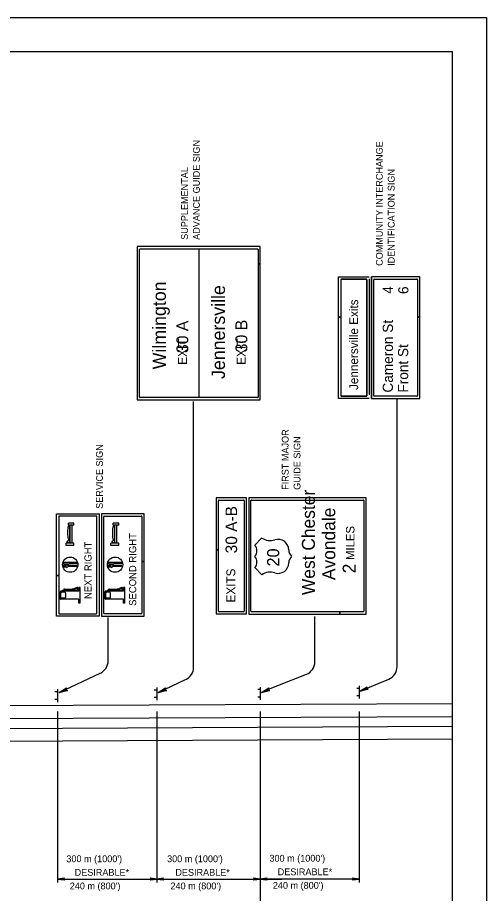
# Model space of a CAD drawing. Extents: x 640994 to 644422, y 298458 to 299646.
# Drawn here: x 644151 to 644358.3, y 299258.5 to 299645.6 of the extents above; entities that cross this region are included whole.
import ezdxf

# ---------------------------------------------------------------- set-up
doc = ezdxf.new("R2010")
doc.units = 0
for name, color, linetype in [('1', 7, 'Continuous'), ('2', 7, 'Continuous'), ('XCS-GRID-MIN', 7, 'Continuous')]:
    doc.layers.add(name, color=color, linetype=linetype)

msp = doc.modelspace()

# ---------------------------------------------------------------- linework, layer by layer
at = {"layer": '1'}
for p in [(643557.31, 299630.63), (644343.31, 299066.63)]:
    msp.add_line(p, (644343.31, 299630.63), dxfattribs=at)
at = {"layer": '2'}
for p, q in [((644258.31, 299544.39), (644203.94, 299544.39)), ((644203.94, 299544.39), (644203.94, 299476.64)), ((644258.31, 299536.79), (644258.31, 299544.39)), ((644204.94, 299477.89), (644204.94, 299543.14)), ((644205.19, 299543.39), (644257.06, 299543.39)), ((644231.19, 299543.39), (644231.19, 299477.64)), ((644257.31, 299543.14), (644257.31, 299536.79)), ((644258.31, 299536.79), (644257.31, 299536.79)), ((644257.31, 299536.79), (644257.31, 299477.89)), ((644257.31, 299536.79), (644258.31, 299536.79)), ((644258.31, 299476.64), (644258.31, 299536.79)), ((644292.94, 299513.21), (644292.94, 299531.02)), ((644292.94, 299531.02), (644306.44, 299531.02)), ((644293.94, 299529.77), (644293.94, 299513.21)), ((644294.19, 299530.02), (644305.19, 299530.02)), ((644305.19, 299530.02), (644294.19, 299530.02)), ((644305.44, 299529.77), (644305.44, 299478.52)), ((644305.44, 299478.52), (644305.44, 299529.77)), ((644306.44, 299530.14), (644306.44, 299478.89)), ((644307.44, 299477.27), (644307.44, 299531.02)), ((644328.81, 299531.02), (644307.44, 299531.02)), ((644307.44, 299531.02), (644307.44, 299477.27)), ((644308.44, 299478.52), (644308.44, 299529.77)), ((644308.44, 299478.52), (644308.44, 299529.77)), ((644308.69, 299530.02), (644327.56, 299530.02)), ((644308.69, 299530.02), (644327.56, 299530.02)), ((644327.81, 299529.77), (644327.81, 299513.28)), ((644328.81, 299513.28), (644328.81, 299531.02)), ((644292.94, 299513.21), (644293.94, 299513.21)), ((644293.94, 299513.21), (644292.94, 299513.21)), ((644292.94, 299477.27), (644292.94, 299513.21)), ((644293.94, 299513.21), (644293.94, 299478.52)), ((644299.69, 299515.27), (644299.69, 299515.27)), ((644327.81, 299513.28), (644328.81, 299513.28)), ((644328.81, 299513.28), (644327.81, 299513.28)), ((644327.81, 299513.28), (644327.81, 299478.52)), ((644328.81, 299477.27), (644328.81, 299513.28)), ((644318.19, 299504.14), (644318.19, 299504.14)), ((644257.06, 299477.64), (644205.19, 299477.64)), ((644305.19, 299478.27), (644294.19, 299478.27)), ((644294.19, 299478.27), (644305.19, 299478.27)), ((644327.56, 299478.27), (644308.69, 299478.27)), ((644327.56, 299478.27), (644308.69, 299478.27)), ((644203.94, 299476.64), (644258.31, 299476.64)), ((644228.81, 299358.52), (644228.81, 299475.89)), ((644306.44, 299477.27), (644292.94, 299477.27)), ((644307.44, 299477.27), (644307.41, 299477.27)), ((644307.44, 299477.27), (644328.81, 299477.27)), ((644318.81, 299358.77), (644318.81, 299476.77)), ((644252.19, 299433.34), (644238.81, 299433.34)), ((644238.81, 299433.34), (644238.81, 299410.41)), ((644239.81, 299410.41), (644239.81, 299432.09)), ((644240.06, 299432.34), (644250.94, 299432.34)), ((644251.19, 299432.09), (644251.19, 299383.31)), ((644252.19, 299382.06), (644252.19, 299433.34)), ((644305.06, 299433.39), (644253.19, 299433.39)), ((644253.19, 299433.39), (644253.19, 299382.02)), ((644254.19, 299383.27), (644254.19, 299432.14)), ((644254.44, 299432.39), (644303.81, 299432.39)), ((644304.06, 299432.14), (644304.06, 299383.27)), ((644305.06, 299382.02), (644305.06, 299433.39)), ((644168.19, 299399.01), (644168.19, 299426.27)), ((644168.19, 299426.27), (644187.06, 299426.27)), ((644169.19, 299425.02), (644169.19, 299399.01)), ((644185.81, 299425.27), (644169.44, 299425.27)), ((644186.06, 299382.39), (644186.06, 299425.02)), ((644187.06, 299426.27), (644187.06, 299381.14)), ((644206.94, 299426.27), (644188.06, 299426.27)), ((644188.06, 299426.27), (644188.06, 299381.14)), ((644189.06, 299382.39), (644189.06, 299425.02)), ((644189.31, 299425.27), (644205.69, 299425.27)), ((644205.94, 299425.02), (644205.94, 299405.17)), ((644206.94, 299405.17), (644206.94, 299426.27)), ((644175.94, 299422.14), (644173.44, 299422.14)), ((644173.44, 299421.27), (644173.44, 299422.14)), ((644175.94, 299421.27), (644173.44, 299421.27)), ((644174.06, 299414.77), (644174.06, 299421.02)), ((644174.31, 299413.27), (644174.31, 299421.27)), ((644175.19, 299413.27), (644175.19, 299421.27)), ((644175.94, 299421.27), (644175.94, 299422.14)), ((644195.81, 299422.14), (644193.31, 299422.14)), ((644193.31, 299421.27), (644193.31, 299422.14)), ((644195.81, 299421.27), (644193.31, 299421.27)), ((644193.94, 299414.77), (644193.94, 299421.02)), ((644194.06, 299413.27), (644194.06, 299421.27)), ((644194.94, 299413.27), (644194.94, 299421.27)), ((644195.81, 299421.27), (644195.81, 299422.14)), ((644174.31, 299417.27), (644174.31, 299417.27)), ((644174.31, 299417.27), (644174.31, 299417.27)), ((644194.06, 299417.27), (644194.06, 299417.27)), ((644194.06, 299417.27), (644194.06, 299417.27)), ((644175.94, 299413.27), (644172.44, 299413.27)), ((644172.44, 299412.27), (644172.44, 299413.27)), ((644175.94, 299412.27), (644172.44, 299412.27)), ((644175.94, 299412.27), (644175.94, 299413.27)), ((644195.81, 299413.27), (644192.19, 299413.27)), ((644192.19, 299412.27), (644192.19, 299413.27)), ((644195.81, 299412.27), (644192.19, 299412.27)), ((644195.81, 299412.27), (644195.81, 299413.27)), ((644255.94, 299412.52), (644259.06, 299415.64)), ((644266.19, 299415.02), (644266.19, 299415.02)), ((644239.81, 299410.41), (644238.81, 299410.41)), ((644238.81, 299410.41), (644238.81, 299382.06)), ((644238.81, 299410.41), (644239.81, 299410.41)), ((644239.81, 299383.31), (644239.81, 299410.41)), ((644270.94, 299410.39), (644270.94, 299410.39)), ((644177.06, 299404.77), (644171.31, 299404.77)), ((644171.31, 299404.77), (644171.31, 299404.39)), ((644177.06, 299404.27), (644174.06, 299404.27)), ((644196.81, 299404.77), (644191.06, 299404.77)), ((644191.06, 299404.77), (644191.06, 299404.39)), ((644196.81, 299404.27), (644193.94, 299404.27)), ((644205.94, 299405.17), (644206.94, 299405.17)), ((644206.94, 299405.17), (644205.94, 299405.17)), ((644205.94, 299405.17), (644205.94, 299382.39)), ((644206.94, 299381.14), (644206.94, 299405.17)), ((644264.19, 299407.52), (644264.19, 299407.52)), ((644264.19, 299407.52), (644264.19, 299407.52)), ((644270.94, 299404.64), (644270.94, 299404.64)), ((644171.19, 299403.52), (644172.44, 299403.77)), ((644172.56, 299403.52), (644171.19, 299403.52)), ((644171.19, 299403.02), (644172.31, 299403.14)), ((644172.69, 299402.89), (644171.19, 299403.02)), ((644172.56, 299402.64), (644171.19, 299402.89)), ((644171.19, 299402.89), (644172.69, 299402.89)), ((644171.31, 299403.39), (644172.56, 299403.52)), ((644172.56, 299403.27), (644171.31, 299403.39)), ((644173.44, 299404.02), (644171.81, 299404.02)), ((644172.31, 299403.14), (644172.56, 299403.27)), ((644177.06, 299403.39), (644173.56, 299403.39)), ((644177.06, 299403.02), (644173.56, 299403.02)), ((644174.31, 299403.77), (644174.31, 299403.77)), ((644174.31, 299403.77), (644174.31, 299403.77)), ((644177.69, 299403.77), (644177.69, 299403.77)), ((644191.06, 299403.52), (644192.19, 299403.77)), ((644191.06, 299403.39), (644192.44, 299403.52)), ((644192.44, 299403.52), (644191.06, 299403.52)), ((644192.44, 299403.27), (644191.06, 299403.39)), ((644191.06, 299403.02), (644192.19, 299403.14)), ((644192.44, 299402.89), (644191.06, 299403.02)), ((644192.31, 299402.64), (644191.06, 299402.89)), ((644191.06, 299402.89), (644192.44, 299402.89)), ((644193.19, 299404.02), (644191.56, 299404.02)), ((644192.19, 299403.14), (644192.44, 299403.27)), ((644196.81, 299403.39), (644193.31, 299403.39)), ((644196.81, 299403.02), (644193.31, 299403.02)), ((644194.06, 299403.77), (644194.06, 299403.77)), ((644194.06, 299403.77), (644194.06, 299403.77)), ((644197.44, 299403.77), (644197.44, 299403.77)), ((644259.06, 299399.39), (644255.94, 299402.52)), ((644168.19, 299381.14), (644168.19, 299399.01)), ((644168.19, 299399.01), (644169.19, 299399.01)), ((644169.19, 299399.01), (644168.19, 299399.01)), ((644169.19, 299399.01), (644169.19, 299382.39)), ((644170.56, 299392.14), (644171.19, 299392.77)), ((644171.81, 299393.02), (644174.94, 299393.02)), ((644172.06, 299392.77), (644174.94, 299392.77)), ((644172.06, 299392.77), (644172.06, 299392.27)), ((644173.44, 299392.52), (644176.81, 299392.52)), ((644175.56, 299393.14), (644176.44, 299393.52)), ((644175.81, 299392.89), (644176.56, 299393.14)), ((644178.06, 299392.14), (644178.06, 299393.77)), ((644178.69, 299393.77), (644178.06, 299393.77)), ((644178.69, 299386.77), (644178.69, 299393.77)), ((644190.44, 299392.14), (644191.06, 299392.77)), ((644191.56, 299393.02), (644194.81, 299393.02)), ((644191.81, 299392.77), (644194.81, 299392.77)), ((644191.81, 299392.77), (644191.81, 299392.27)), ((644193.31, 299392.52), (644196.56, 299392.52)), ((644195.44, 299393.14), (644196.19, 299393.52)), ((644195.56, 299392.89), (644196.31, 299393.14)), ((644197.81, 299392.14), (644197.81, 299393.77)), ((644198.44, 299393.77), (644197.81, 299393.77)), ((644198.44, 299386.77), (644198.44, 299393.77)), ((644169.81, 299389.02), (644169.81, 299391.64)), ((644178.06, 299392.14), (644170.06, 299392.14)), ((644170.19, 299389.27), (644170.19, 299391.39)), ((644171.94, 299391.64), (644170.44, 299391.64)), ((644171.94, 299389.02), (644170.44, 299389.02)), ((644172.06, 299392.27), (644171.19, 299392.27)), ((644171.19, 299392.27), (644171.19, 299392.14)), ((644172.31, 299389.27), (644172.31, 299391.27)), ((644173.19, 299392.14), (644173.19, 299392.27)), ((644173.44, 299392.14), (644173.44, 299392.14)), ((644173.56, 299392.27), (644177.06, 299392.27)), ((644174.31, 299390.39), (644174.31, 299390.39)), ((644174.31, 299390.39), (644174.31, 299390.39)), ((644189.56, 299389.02), (644189.56, 299391.64)), ((644197.81, 299392.14), (644189.94, 299392.14)), ((644190.06, 299389.27), (644190.06, 299391.39)), ((644191.81, 299391.64), (644190.19, 299391.64)), ((644191.81, 299389.02), (644190.19, 299389.02)), ((644191.06, 299392.27), (644190.94, 299392.14)), ((644191.81, 299392.27), (644191.06, 299392.27)), ((644192.06, 299389.27), (644192.06, 299391.27)), ((644192.94, 299392.14), (644192.94, 299392.27)), ((644193.31, 299392.14), (644193.31, 299392.14)), ((644193.44, 299392.27), (644196.94, 299392.27)), ((644194.06, 299390.39), (644194.06, 299390.39)), ((644194.06, 299390.39), (644194.06, 299390.39)), ((644178.06, 299388.52), (644170.06, 299388.52)), ((644178.06, 299386.77), (644178.06, 299388.52)), ((644178.69, 299386.77), (644178.06, 299386.77)), ((644197.81, 299388.52), (644189.94, 299388.52)), ((644197.81, 299386.77), (644197.81, 299388.52)), ((644198.44, 299386.77), (644197.81, 299386.77)), ((644187.06, 299381.14), (644168.19, 299381.14)), ((644169.44, 299382.14), (644185.81, 299382.14)), ((644188.06, 299381.14), (644206.94, 299381.14)), ((644205.69, 299382.14), (644189.31, 299382.14)), ((644238.81, 299382.06), (644252.19, 299382.06)), ((644250.94, 299383.06), (644240.06, 299383.06)), ((644253.19, 299382.02), (644293.51, 299382.02)), ((644293.51, 299383.02), (644254.44, 299383.02)), ((644282.44, 299360.89), (644282.44, 299380.89)), ((644293.51, 299383.02), (644293.51, 299382.02)), ((644293.51, 299382.02), (644293.51, 299383.02)), ((644303.81, 299383.02), (644293.51, 299383.02)), ((644293.51, 299382.02), (644305.06, 299382.02)), ((644191.06, 299361.39), (644191.06, 299380.52)), ((644169.44, 299347.39), (644187.56, 299355.89)), ((644259.69, 299347.89), (644278.69, 299355.39)), ((644213.19, 299347.39), (644225.31, 299353.02)), ((644302.06, 299350.27), (644302.06, 299344.64)), ((644302.31, 299347.89), (644315.19, 299353.27)), ((644168.69, 299347.64), (644167.44, 299347.64)), ((644168.69, 299348.77), (644168.69, 299343.14)), ((644212.56, 299348.39), (644211.44, 299348.39)), ((644212.56, 299349.52), (644212.56, 299344.02)), ((644258.31, 299348.64), (644257.19, 299348.64)), ((644258.31, 299349.77), (644258.31, 299344.14)), ((644302.06, 299349.14), (644300.94, 299349.14)), ((644343.31, 299342.27), (643974.31, 299340.64)), ((644168.69, 299344.27), (644167.44, 299344.27)), ((644212.56, 299345.14), (644211.44, 299345.14)), ((644258.31, 299345.27), (644257.19, 299345.27)), ((644302.06, 299345.89), (644300.94, 299345.89)), ((644168.69, 299339.02), (644168.69, 299263.39)), ((644212.56, 299339.02), (644212.56, 299263.39)), ((644258.31, 299339.02), (644258.31, 299263.39)), ((644302.06, 299339.02), (644302.06, 299263.39)), ((644343.31, 299336.65), (643825.94, 299334.39)), ((644343.31, 299332.27), (643825.19, 299329.89)), ((644343.31, 299326.65), (643987.69, 299325.02)), ((644319.69, 299326.52), (644319.69, 299326.52)), ((644258.31, 299314.64), (644258.31, 299236.52)), ((644168.69, 299264.89), (644212.56, 299264.89)), ((644212.56, 299264.89), (644258.31, 299264.89)), ((644302.06, 299264.89), (644258.31, 299264.89)), ((644258.31, 299264.89), (644267.81, 299264.89))]:
    msp.add_line(p, q, dxfattribs=at)
for points in [[(644305.69, 299348.77), (644305.56, 299349.02), (644302.31, 299347.89), (644305.69, 299348.77), (644306.06, 299348.77), (644302.31, 299347.89), (644305.31, 299349.39), (644305.44, 299349.64), (644302.31, 299347.89), (644305.56, 299349.89), (644305.44, 299349.64)], [(644172.81, 299348.27), (644172.69, 299348.52), (644169.44, 299347.39), (644172.81, 299348.27), (644173.19, 299348.27), (644169.44, 299347.39), (644172.44, 299348.89), (644172.56, 299349.14), (644169.44, 299347.39), (644172.69, 299349.39), (644172.56, 299349.14)], [(644216.56, 299348.27), (644216.44, 299348.52), (644213.19, 299347.39), (644216.56, 299348.27), (644216.94, 299348.27), (644213.19, 299347.39), (644216.19, 299348.89), (644216.31, 299349.14), (644213.19, 299347.39), (644216.44, 299349.39), (644216.31, 299349.14)], [(644262.19, 299348.27), (644262.06, 299348.52), (644258.81, 299347.39), (644262.19, 299348.27), (644262.56, 299348.27), (644258.81, 299347.39), (644261.81, 299348.89), (644261.94, 299349.14), (644258.81, 299347.39), (644262.06, 299349.39), (644261.94, 299349.14)], [(644171.54, 299264.53), (644171.43, 299264.74), (644168.69, 299264.89), (644171.54, 299264.53), (644171.69, 299264.41), (644168.69, 299264.89), (644171.43, 299265.03), (644171.53, 299265.23), (644168.69, 299264.89), (644171.69, 299265.37), (644171.53, 299265.23)], [(644209.71, 299265.25), (644209.81, 299265.04), (644212.56, 299264.89), (644209.71, 299265.25), (644209.56, 299265.37), (644212.56, 299264.89), (644209.82, 299264.76), (644209.72, 299264.55), (644212.56, 299264.89), (644209.56, 299264.41), (644209.72, 299264.55)], [(644215.42, 299264.53), (644215.31, 299264.74), (644212.56, 299264.89), (644215.42, 299264.53), (644215.56, 299264.41), (644212.56, 299264.89), (644215.31, 299265.03), (644215.41, 299265.23), (644212.56, 299264.89), (644215.56, 299265.37), (644215.41, 299265.23)], [(644255.46, 299265.25), (644255.56, 299265.04), (644258.31, 299264.89), (644255.46, 299265.25), (644255.31, 299265.37), (644258.31, 299264.89), (644255.57, 299264.76), (644255.47, 299264.55), (644258.31, 299264.89), (644255.31, 299264.41), (644255.47, 299264.55)], [(644261.17, 299264.53), (644261.06, 299264.74), (644258.31, 299264.89), (644261.17, 299264.53), (644261.31, 299264.41), (644258.31, 299264.89), (644261.06, 299265.03), (644261.16, 299265.23), (644258.31, 299264.89), (644261.31, 299265.37), (644261.16, 299265.23)], [(644299.21, 299265.25), (644299.31, 299265.04), (644302.06, 299264.89), (644299.21, 299265.25), (644299.06, 299265.37), (644302.06, 299264.89), (644299.32, 299264.76), (644299.22, 299264.55), (644302.06, 299264.89), (644299.06, 299264.41), (644299.22, 299264.55)]]:
    msp.add_lwpolyline(points, dxfattribs=at)
for centre, radius in [((644173.54, 299413.99), 0.598), ((644193.35, 299413.99), 0.598), ((644174.27, 299403.83), 3.38), ((644194.08, 299403.83), 3.38)]:
    msp.add_circle(centre, radius, dxfattribs=at)
for centre, radius, start, end in [((644205.19, 299543.14), 0.25, 90, 180), ((644257.06, 299543.14), 0.25, 0, 90), ((644294.19, 299529.77), 0.25, 90, 180), ((644294.19, 299529.77), 0.25, 90, 180), ((644305.19, 299529.77), 0.25, 0, 90), ((644305.19, 299529.77), 0.25, 0, 90), ((644308.69, 299529.77), 0.25, 90, 180), ((644308.69, 299529.77), 0.25, 90, 180), ((644327.56, 299529.77), 0.25, 0, 90), ((644327.56, 299529.77), 0.25, 0, 90), ((644205.19, 299477.89), 0.25, 180, 270), ((644257.06, 299477.89), 0.25, 270, 0), ((644294.19, 299478.52), 0.25, 180, 270), ((644294.19, 299478.52), 0.25, 180, 270), ((644305.19, 299478.52), 0.25, 270, 0), ((644305.19, 299478.52), 0.25, 270, 0), ((644308.69, 299478.52), 0.25, 180, 270), ((644308.69, 299478.52), 0.25, 180, 270), ((644327.56, 299478.52), 0.25, 270, 0), ((644327.56, 299478.52), 0.25, 270, 0), ((644240.06, 299432.09), 0.25, 90, 180), ((644250.94, 299432.09), 0.25, 0, 90), ((644254.44, 299432.14), 0.25, 90, 180), ((644303.81, 299432.14), 0.25, 0, 90), ((644169.44, 299425.02), 0.25, 90, 180), ((644185.81, 299425.02), 0.25, 0, 90), ((644189.31, 299425.02), 0.25, 90, 180), ((644205.69, 299425.02), 0.25, 0, 90), ((644188.64, 299417.98), 15.54, 171.2295, 181.1783), ((644174.02, 299420.26), 0.74, 84.1655, 172.9293), ((644208.45, 299417.98), 15.54, 171.2295, 181.1783), ((644193.83, 299420.26), 0.74, 84.1655, 172.9293), ((644191.86, 299417.93), 18.75, 180.8408, 188.1781), ((644211.67, 299417.93), 18.75, 180.8408, 188.1781), ((644174.1, 299415.6), 0.868, 202.8419, 269.9082), ((644193.91, 299415.6), 0.868, 202.8419, 269.9082), ((644252.6, 299410.01), 4.18, 323.136, 36.864), ((644262.74, 299420.97), 6.5, 235.4253, 288.1711), ((644266.25, 299410.37), 4.66, 0.0047, 108.548), ((644274.85, 299410.37), 3.94, 180, 226.2725), ((644171.76, 299404.44), 0.422, 180, 270), ((644173.25, 299404.7), 0.696, 281.1263, 314.137), ((644174.01, 299403.95), 0.369, 83.1408, 137.1102), ((644177.09, 299404.53), 0.218, 261.5053, 98.4947), ((644191.57, 299404.44), 0.422, 180, 270), ((644193.06, 299404.7), 0.696, 281.1263, 314.137), ((644193.82, 299403.95), 0.369, 83.1408, 137.1102), ((644196.9, 299404.53), 0.218, 261.5053, 98.4947), ((644252.6, 299405), 4.18, 323.136, 36.864), ((644266.25, 299404.64), 4.66, 251.452, 359.9953), ((644274.85, 299404.64), 3.94, 133.7275, 180), ((644172.64, 299402.94), 0.83, 44.7019, 103.537), ((644172.7, 299403.37), 0.724, 261.5401, 313.94), ((644173.58, 299402.53), 0.494, 95.8318, 139.6318), ((644173.53, 299403.82), 0.42, 224.9301, 269.654), ((644177.1, 299403.21), 0.195, 258.6255, 101.3745), ((644192.45, 299402.94), 0.83, 44.7019, 103.537), ((644192.51, 299403.37), 0.724, 261.5401, 313.94), ((644193.39, 299402.53), 0.494, 95.8318, 139.6318), ((644193.34, 299403.82), 0.42, 224.9301, 269.654), ((644196.91, 299403.21), 0.195, 258.6255, 101.3745), ((644262.74, 299394.05), 6.5, 71.8289, 124.5747), ((644171.85, 299392.2), 0.826, 95.5404, 137.2088), ((644173.45, 299392.25), 0.265, 89.4256, 167.8581), ((644174.73, 299395.49), 2.48, 276.6108, 292.2765), ((644174.73, 299395.49), 2.79, 276.6108, 292.2765), ((644177.37, 299391.45), 2.24, 92.3973, 115.3499), ((644177.14, 299391.97), 1.32, 82.2446, 117.6633), ((644176.71, 299393.79), 1.27, 271.1053, 299.4807), ((644177.12, 299393.02), 0.794, 269.2148, 356.6422), ((644177.22, 299392.98), 0.7, 359.2139, 85.3444), ((644177.23, 299392.98), 0.318, 289.9687, 73.0966), ((644191.66, 299392.2), 0.826, 95.5404, 137.2088), ((644193.26, 299392.25), 0.265, 89.4256, 167.8581), ((644194.54, 299395.49), 2.48, 276.6108, 292.2765), ((644194.54, 299395.49), 2.79, 276.6108, 292.2765), ((644197.18, 299391.45), 2.24, 92.3973, 115.3499), ((644196.95, 299391.97), 1.32, 82.2446, 117.6633), ((644196.52, 299393.79), 1.27, 271.1053, 299.4807), ((644196.93, 299393.02), 0.794, 269.2148, 356.6422), ((644197.03, 299392.98), 0.7, 359.2139, 85.3444), ((644197.04, 299392.98), 0.318, 289.9687, 73.0966), ((644170.17, 299391.67), 0.405, 97.9024, 178.9277), ((644170.11, 299388.93), 0.346, 171.6254, 276.5874), ((644170.41, 299389.23), 0.207, 168.286, 258.2569), ((644170.44, 299391.42), 0.228, 107.0861, 183.3769), ((644171.92, 299391.32), 0.327, 355.7148, 73.5391), ((644171.98, 299389.28), 0.262, 276.241, 356.6554), ((644173.54, 299392.16), 0.0642, 79.1965, 181.8396), ((644189.98, 299391.67), 0.405, 97.9024, 178.9277), ((644189.92, 299388.93), 0.346, 171.6254, 276.5874), ((644190.25, 299391.42), 0.228, 107.0861, 183.3769), ((644190.22, 299389.23), 0.207, 168.286, 258.2569), ((644191.73, 299391.32), 0.327, 355.7148, 73.5391), ((644191.8, 299389.28), 0.262, 276.241, 356.6554), ((644193.36, 299392.16), 0.0642, 79.1965, 181.8396), ((644169.44, 299382.39), 0.25, 180, 270), ((644185.81, 299382.39), 0.25, 270, 0), ((644189.31, 299382.39), 0.25, 180, 270), ((644205.69, 299382.39), 0.25, 270, 0), ((644240.06, 299383.31), 0.25, 180, 270), ((644250.94, 299383.31), 0.25, 270, 0), ((644254.44, 299383.27), 0.25, 180, 270), ((644303.81, 299383.27), 0.25, 270, 0), ((644185.06, 299361.35), 6, 295.1448, 0), ((644222.81, 299358.5), 6, 295.1077, 0), ((644276.44, 299360.92), 6, 291.4477, 0), ((644312.81, 299358.79), 6, 292.6938, 0)]:
    msp.add_arc(centre, radius, start, end, dxfattribs=at)
at = {"layer": 'XCS-GRID-MIN'}
msp.add_lwpolyline([(643517.31, 299645.63), (644358.31, 299645.63), (644358.31, 299051.63), (643517.31, 299051.63)], close=True, dxfattribs=at)

# ---------------------------------------------------------------- texts
at = {"layer": '2'}
for s, height, p in [('ADVANCE GUIDE SIGN', 3, (644231.56, 299547.39)), ('COMMUNITY INTERCHANGE', 3, (644312.44, 299535.89)), ('SUPPLEMENTAL', 3, (644226.31, 299547.39)), ('IDENTIFICATION SIGN', 3, (644317.69, 299535.89)), ('Wilmington', 5.875, (644216.56, 299490.14)), ('Jennersville', 5.8747, (644242.69, 299485.89)), (' 4', 4.5, (644316.94, 299521.89)), (' 6', 4.5, (644323.81, 299521.77)), ('Jennersville Exits', 3.8752, (644301.56, 299481.02)), ('     30 A', 5.21, (644226.45, 299487.65)), ('     30 B', 5.25, (644252.56, 299487.89)), ('Cameron St     ', 4.5, (644316.94, 299479.89)), ('EXIT    ', 3.918, (644225.83, 299492.12)), ('EXIT    ', 3.918, (644251.83, 299492.12)), ('Front St       ', 4.5, (644323.69, 299479.89)), ('FIRST MAJOR', 3, (644270.81, 299436.89)), ('GUIDE SIGN', 3, (644276.06, 299436.89)), ('SERVICE SIGN', 3, (644188.69, 299428.52)), ('West Chester', 5.7435, (644282.44, 299390.39)), ('30 A-B', 5.125, (644248.06, 299408.82)), ('Avondale', 5.743, (644291.44, 299397.02)), ('MILES', 3.75, (644299.94, 299405.89)), ('SECOND RIGHT', 3.1342, (644203.44, 299385.64)), ('NEXT RIGHT', 3.134, (644183.69, 299388.64)), ('20', 5.375, (644266.69, 299403.02)), ('EXITS', 3.875, (644247.21, 299387.12)), ('2', 5.74, (644300.44, 299400.02))]:
    msp.add_text(s, height=height, rotation=90, dxfattribs=at).set_placement(p)
for s, p in [("300 m (1000')", (644172.57, 299272.36)), ("300 m (1000')", (644217.1, 299272.36)), ("300 m (1000')", (644262.36, 299272.6)), ('DESIRABLE*', (644176.22, 299266.36)), ('DESIRABLE*', (644220.75, 299266.36)), ('DESIRABLE*', (644266.01, 299266.6)), ("240 m (800')", (644174.07, 299260.36)), ("240 m (800')", (644218.6, 299260.36)), ("240 m (800')", (644263.86, 299260.6))]:
    msp.add_text(s, height=3, dxfattribs=at).set_placement(p)

doc.saveas('drawing.dxf')
